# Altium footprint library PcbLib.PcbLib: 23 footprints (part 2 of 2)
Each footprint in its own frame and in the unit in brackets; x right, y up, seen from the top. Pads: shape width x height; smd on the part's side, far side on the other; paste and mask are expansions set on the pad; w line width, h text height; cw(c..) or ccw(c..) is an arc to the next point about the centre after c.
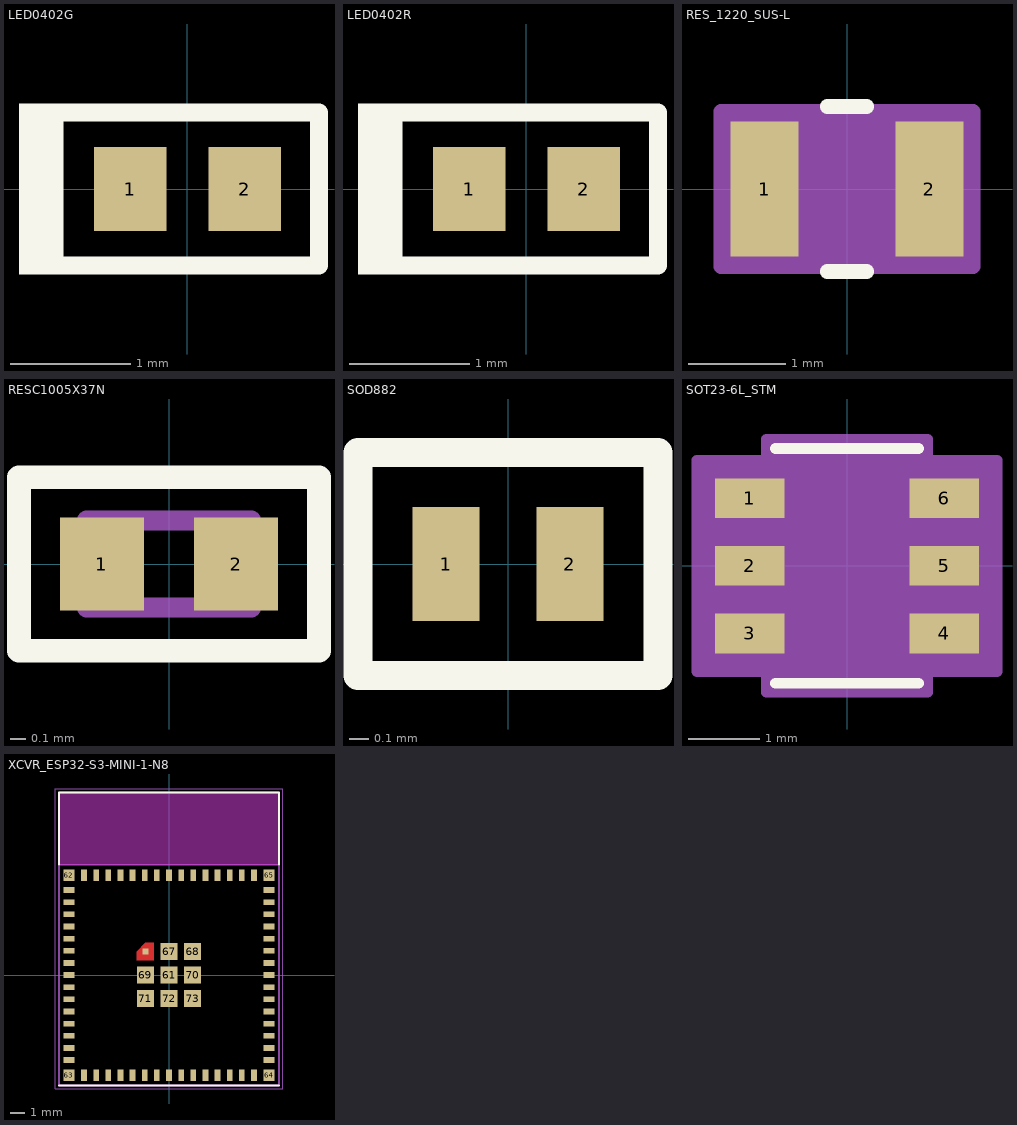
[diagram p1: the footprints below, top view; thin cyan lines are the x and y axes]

## LED0402G [mm]
pads (2):
  rect 0.6x0.7 smd: 1(-0.475,0) 2(0.475,0)
Top Overlay:
  rectangle: -1.397,-0.711 -1.027,0.711
  lines w0.152: -1.295,-0.635 1.092,-0.635 1.092,0.635 -1.295,0.635 -1.295,-0.635
3D body "User Library-LED_1006_G.STEP": height 0.21, standoff 0.01, extent -0.5,-0.3 0.5,0.3

## LED0402R [mm]
pads (2):
  rect 0.6x0.7 smd: 1(-0.475,0) 2(0.475,0)
Top Overlay:
  rectangle: -1.397,-0.711 -1.027,0.711
  lines w0.152: -1.295,-0.635 -1.295,0.635 1.092,0.635 1.092,-0.635 -1.295,-0.635
3D body "User Library-LED_1006_R.STEP": height 0.21, standoff 0.01, extent -0.5,-0.3 0.5,0.3

## RES_1220_SUS-L [mm]
pads (2):
  rect 0.702x1.399 smd paste+0 mask+0: 1(-0.851,0) 2(0.851,0)
Top Overlay:
  lines w0.152: -0.204,-0.852 0.204,-0.852 ; -0.204,0.852 0.204,0.852
Top 3D Body:
  lines w0.025: -1.1,-0.725 -1.1,0.725 ; -1.1,-0.725 -0.5,-0.725 -0.5,0.725 -1.1,0.725 ; -1.1,-0.725 1.1,-0.725 ; -1.1,-0.725 -1.1,0.725 ; -1.1,0.725 1.1,0.725 ; 1.1,-0.725 0.5,-0.725 0.5,0.725 1.1,0.725 ; 1.1,-0.725 1.1,0.725 ; 1.1,-0.725 1.1,0.725
Top Courtyard:
  region: 1.303,-0.801 -1.303,-0.801 -1.303,0.801 1.303,0.801
  lines w0.152: -1.303,-0.801 -1.303,0.801 1.303,0.801 1.303,-0.801 -1.303,-0.801
3D body "RES_1220_SUS.step": height 0.7, standoff 0, extent -1.1,-0.725 1.1,0.725

## RESC1005X37N [mm]
pads (2):
  rect 0.54x0.6 smd: 1(-0.432,0) 2(0.432,0)
Top Overlay:
  lines w0.152: -0.965,-0.559 0.965,-0.559 0.965,0.559 -0.965,0.559 -0.965,-0.559
Top 3D Body:
  lines w0.127: -0.53,-0.28 0.53,-0.28 0.53,0.28 -0.53,0.28 -0.53,-0.28
Top Courtyard:
  lines w0.05: -0.95,-0.55 0.95,-0.55 0.95,0.55 -0.95,0.55 -0.95,-0.55
3D body "step_temp.STEP": height 0.37, standoff 0, extent -0.5,-0.25 0.5,0.25

## SOD882 [mm]
pads (2):
  rect 0.35x0.6 smd: 1(-0.325,0) 2(0.325,0)
Top Overlay:
  lines w0.152: -0.787,-0.584 -0.787,0.584 0.787,0.584 0.787,-0.584 -0.787,-0.584
3D body "AQ3045-01ETG.stp": height 0.44, standoff 0.01, extent -0.535,-0.335 0.535,0.34

## SOT23-6L_STM [mil]
pads (6):
  rect 38.5x22 smd paste+0 mask+0: 1(-53.75,37.4) 2(-53.75,0) 3(-53.75,-37.4) 4(53.75,-37.4) 5(53.75,0) 6(53.75,37.4)
Top Overlay:
  lines w6: -39.5,-65 39.5,-65 ; -39.5,65 39.5,65
Top 3D Body:
  lines w0: -12,60 ccw(c0,60) 12,60
  lines w1: -59,-47.4 -59,-27.4 -34.5,-27.4 -34.5,-47.4 -59,-47.4 ; -59,-10 -59,10 -34.5,10 -34.5,-10 -59,-10 ; -59,27.4 -59,47.4 -34.5,47.4 -34.5,27.4 -59,27.4 ; -34.5,-60 34.5,-60 34.5,60 -34.5,60 -34.5,-60 ; 34.5,-47.4 34.5,-27.4 59,-27.4 59,-47.4 34.5,-47.4 ; 34.5,-10 34.5,10 59,10 59,-10 34.5,-10 ; 34.5,27.4 34.5,47.4 59,47.4 59,27.4 34.5,27.4
  text "*" at -32,7 h50
Top Courtyard:
  region: -44.5,-58.4 -83,-58.4 -83,58.4 -44.5,58.4 -44.5,70 44.5,70 44.5,58.4 83,58.4 83,-58.4 44.5,-58.4 44.5,-70 -44.5,-70
  lines w6: -83,-58.4 -83,58.4 -44.5,58.4 -44.5,70 44.5,70 44.5,58.4 83,58.4 83,-58.4 44.5,-58.4 44.5,-70 -44.5,-70 -44.5,-58.4 -83,-58.4
3D body "SOT23-6L_STM.step": height 57.09, standoff 0, extent -59.02,-60 59.02,60

## XCVR_ESP32-S3-MINI-1-N8 [mm]
height 2.55
pads (73):
  rect 0.8x0.4 smd: 1(-7,5.95) 2(-7,5.1) 3(-7,4.25) 4(-7,3.4) 5(-7,2.55) 6(-7,1.7) 7(-7,0.85) 8(-7,0) 9(-7,-0.85) 10(-7,-1.7) 11(-7,-2.55) 12(-7,-3.4) 13(-7,-4.25) 14(-7,-5.1) 15(-7,-5.95) 31(7,-5.95) 32(7,-5.1) 33(7,-4.25) 34(7,-3.4) 35(7,-2.55) 36(7,-1.7) 37(7,-0.85) 38(7,0) 39(7,0.85) 40(7,1.7) 41(7,2.55) 42(7,3.4) 43(7,4.25) 44(7,5.1) 45(7,5.95)
  rect 0.4x0.8 smd: 16(-5.95,-7) 17(-5.1,-7) 18(-4.25,-7) 19(-3.4,-7) 20(-2.55,-7) 21(-1.7,-7) 22(-0.85,-7) 23(0,-7) 24(0.85,-7) 25(1.7,-7) 26(2.55,-7) 27(3.4,-7) 28(4.25,-7) 29(5.1,-7) 30(5.95,-7) 46(5.95,7) 47(5.1,7) 48(4.25,7) 49(3.4,7) 50(2.55,7) 51(1.7,7) 52(0.85,7) 53(0,7) 54(-0.85,7) 55(-1.7,7) 56(-2.55,7) 57(-3.4,7) 58(-4.25,7) 59(-5.1,7) 60(-5.95,7)
  rect 1.2x1.2 smd: 61(0,0) 67(0,1.65) 68(1.65,1.65) 69(-1.65,0) 70(1.65,0) 71(-1.65,-1.65) 72(0,-1.65) 73(1.65,-1.65)
  rect 0.8x0.8 smd: 62(-7,7) 63(-7,-7) 64(7,-7) 65(7,7)
  rect 0.4x0.4 smd paste-1 mask+0: 66(-1.65,1.65)
Top Layer:
  region: -1.05,1.05 -2.25,1.05 -2.25,1.65 -1.65,2.25 -1.05,2.25
Top Overlay:
  lines w0.127: -7.7,-7.725 7.7,-7.725 ; -7.7,7.725 -7.7,12.775 7.7,12.775 7.7,7.725
Top Paste:
  region: -1.05,1.05 -2.25,1.05 -2.25,1.65 -1.65,2.25 -1.05,2.25
Top Solder:
  region: -0.95,0.95 -2.35,0.95 -2.35,1.7 -1.7,2.35 -0.95,2.35
Keep-Out Layer:
  region: 7.7,7.725 -7.7,7.725 -7.7,12.775 7.7,12.775
  region: 7.7,7.725 -7.7,7.725 -7.7,12.775 7.7,12.775
Top 3D Body:
  lines w0.127: -7.7,7.725 7.7,7.725 ; -7.7,7.725 -7.7,12.775 7.7,12.775 7.7,7.725 ; -7.7,7.725 -7.7,-7.725 7.7,-7.725 7.7,7.725
Top Courtyard:
  lines w0.05: -7.95,-7.975 7.95,-7.975 7.95,13.025 -7.95,13.025 -7.95,-7.975
3D body "step_temp.STEP": height 2.55, standoff 0, extent -7.7,-7.725 7.7,12.775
